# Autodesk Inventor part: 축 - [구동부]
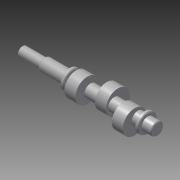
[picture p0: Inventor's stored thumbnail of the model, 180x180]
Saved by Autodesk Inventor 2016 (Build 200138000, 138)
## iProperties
Company: 한국ATC센터
Created: 2014-08
Part Number: 축 - [구동부]
Document SubType Name: Modeling
Designer: mdu
Density: 7.86 g/cm^3
Material: 강철, 연강
Mass: 493.099 g
Surface Area: 158.63 cm^2
Volume: 62.7352 cm^3
Appearance: 강철
Author: mdu
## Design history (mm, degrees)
sketch "스케치1"
  geometry: L1 (-91.5, 0)-(91.5, 0); L2 (-91.5, 0)-(-91.5, 6.5); L3 (-59.681, 8.5)-(-27.5, 8.5); L4 (-27.5, 8.5)-(-27.5, 13); L5 (-27.5, 13)-(-22.5, 13); L6 (-22.5, 13)-(-22.5, 8.5); L7 (-22.5, 8.5)-(73.5, 8.5); L8 (73.5, 8.5)-(73.5, 13); L9 (73.5, 13)-(78.5, 13); L10 (78.5, 13)-(78.5, 8.5); L11 (78.5, 8.5)-(91.5, 8.5); L12 (91.5, 8.5)-(91.5, 0); L13 (-61.5, 7.45)-(-61.5, 6.5); L14 (-61.5, 6.5)-(-91.5, 6.5); L15 (-61.5, 7.45)-(-59.681, 8.5); 2 further points
  constraints: 30 end point, 6 parallel, 2 perpendicular, 1 coincident, 1 horizontal, 1 midpoint
  dimensions: "d0" = 183 distance of L1.start L1.end (derived); "d2" = 17 diameter of L3 L1; "d3" = 26 diameter of L5 L1; "d4" = 17 diameter of L7 L1; "d5" = 26 diameter of L9 L1; "d6" = 17 diameter of L11 L1; "d7" = 5 distance of L8.end L9.end; "d8" = 5 distance of L4.end L5.end; "d11" = 13 distance of L10.end L11.end; "d35" = 96 distance between parallel lines of L8 L6; "d57" = 13 diameter of L14 L1; "d58" = 64 distance between parallel lines of L4 L2; "d60" = 30 horizontal distance of L2.end L13.start; "d61" = 14.9 diameter of L13.start L1; "d62" = 30 deg angle of L3 L15
revolve "회전1" sketch "스케치1" stored, may be unused: angle "d12" = 90 deg
node "작업 평면7"
sketch "스케치6"
  geometry: C1 r 15 at (0, 5); 1 further point
  constraints: 1 centre point, 1 vertical alignment
  dimensions: "d37" = 30 diameter of C1; "d38" = 5 distance of C1.centre point (0, 0)
extrude "돌출4" join sketch "스케치6" stored distance "d33" = 15; taper "d34" = 0 deg
node "작업 평면8"
sketch "스케치7"
  geometry: L1 (0, 0)-(-6.5, -11.258); L2 (0, 0)-(13, 0); C1 r 15 at (-2.5, -4.33); A1 r 13 centre (0, 0) between (-6.5, -11.258) and (13, 0) reference; 1 further point
  constraints: 4 end point, 2 point on circle, 1 centre point, 1 horizontal, 1 point on line
  dimensions: "d40" = 120 deg angle of L1 L2; "d41" = 30 diameter of C1; "d42" = 5 distance of point (0, 0) C1.centre
extrude "돌출5" join sketch "스케치7" stored distance "d43" = 15; taper "d44" = 0 deg
node "작업 평면9"
sketch "스케치8"
  geometry: L1 (0, 0)-(4.25, -7.361); L2 (0, 0)-(-8.5, 0); C1 r 15 at (2.5, -4.33); A1 r 8.5 centre (0, 0) between (4.25, -7.361) and (-8.5, 0) reference; 1 further point
  constraints: 4 end point, 2 point on circle, 1 centre point, 1 horizontal, 1 point on line
  dimensions: "d46" = 120 deg angle of L1 L2; "d47" = 30 diameter of C1; "d48" = 5 distance of point (0, 0) C1.centre
extrude "돌출6" join sketch "스케치8" stored distance "d49" = 15; taper "d50" = 0 deg
node "작업 평면3"
sketch "스케치5"
  geometry: L1 (91.5, 6.5)-(91.5, -6.5) reference; L2 (87, -2.5)-(66, -2.5); L3 (66, 2.5)-(87, 2.5); A1 r 2.5 centre (66, 0) between (66, 2.5) and (66, -2.5); A2 r 2.5 centre (87, 0) between (87, -2.5) and (87, 2.5); 4 further points
  constraints: 4 end point, 4 point on circle, 4 tangent, 2 centre point, 2 point on line, 1 horizontal alignment, 1 midpoint, 1 parallel, 1 perpendicular
  dimensions: "d23" = 5 distance between parallel lines of L3 L2; "d36" = 28 dimension on A1 L1; "d52" = 2 distance edge to line of A2 L1
extrude "돌출3" cut sketch "스케치5" distance "d25" = 3; taper "d26" = 0 deg
chamfer "모따기1" distance "d27" = 1; stored, may be unused: second distance "d28" = 2, angle "d29" = 45 deg
fillet "모깎기1" dims "d51" = 0.3
chamfer "모따기2" distance "d53" = 1; stored, may be unused: second distance "d54" = 2, angle "d55" = 45 deg
node "작업 평면10"
fillet "모깎기2" dims "d63" = 4
fillet "모깎기3" dims "d64" = 1
node "솔리드1"
other parameters: "d39" = -32, "d45" = 32, "d66" = 6.5
